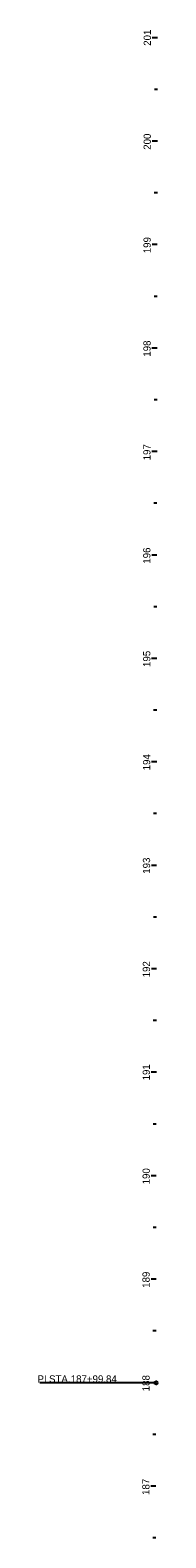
# Model space of a CAD drawing. Extents: x 1805326 to 1810276, y 297762 to 303660.
# Drawn here: x 1808551 to 1808667, y 299219 to 300677 of the extents above; entities that cross this region are included whole.
import ezdxf

# ---------------------------------------------------------------- set-up
doc = ezdxf.new("R2010")
doc.units = 0
doc.layers.add('GE_P_Alignment_100_Cardinal_Points', color=7, linetype='Continuous')
doc.layers.add('GE_P_Alignment_100_Stations', color=7, linetype='Continuous')

msp = doc.modelspace()

# ---------------------------------------------------------------- linework, layer by layer
at = {"layer": 'GE_P_Alignment_100_Cardinal_Points'}
msp.add_line((1808665.1, 299369.1), (1808552.6, 299369.2), dxfattribs=at)
msp.add_circle((1808665.1, 299369.1), 1.5, dxfattribs=at)
at = {"layer": 'GE_P_Alignment_100_Stations'}
for p, q in [((1808666.4, 300669.2), (1808661.4, 300669.2)), ((1808666.4, 300619.2), (1808663.4, 300619.2)), ((1808666.3, 300569.2), (1808661.3, 300569.2)), ((1808666.3, 300519.2), (1808663.3, 300519.2)), ((1808666.2, 300469.2), (1808661.2, 300469.2)), ((1808666.2, 300419.2), (1808663.2, 300419.2)), ((1808666.1, 300369.2), (1808661.1, 300369.2)), ((1808666.1, 300319.2), (1808663.1, 300319.2)), ((1808666, 300269.2), (1808661, 300269.2)), ((1808665.9, 300219.2), (1808662.9, 300219.2)), ((1808665.9, 300169.2), (1808660.9, 300169.2)), ((1808665.8, 300119.2), (1808662.8, 300119.2)), ((1808665.8, 300069.2), (1808660.8, 300069.2)), ((1808665.7, 300019.2), (1808662.7, 300019.2)), ((1808665.7, 299969.2), (1808660.7, 299969.2)), ((1808665.6, 299919.2), (1808662.6, 299919.2)), ((1808665.6, 299869.2), (1808660.6, 299869.2)), ((1808665.5, 299819.2), (1808662.5, 299819.2)), ((1808665.5, 299769.2), (1808660.5, 299769.2)), ((1808665.4, 299719.2), (1808662.4, 299719.2)), ((1808665.4, 299669.2), (1808660.4, 299669.2)), ((1808665.3, 299619.2), (1808662.3, 299619.2)), ((1808665.3, 299569.2), (1808660.3, 299569.2)), ((1808665.2, 299519.2), (1808662.2, 299519.2)), ((1808665.2, 299469.2), (1808660.2, 299469.2)), ((1808665.1, 299419.2), (1808662.1, 299419.2)), ((1808665.1, 299369.2), (1808660.1, 299369.2)), ((1808665, 299319.2), (1808662, 299319.2)), ((1808665, 299269.2), (1808660, 299269.2)), ((1808664.9, 299219.2), (1808661.9, 299219.2))]:
    msp.add_line(p, q, dxfattribs=at)

# ---------------------------------------------------------------- texts
at = {"layer": 'GE_P_Alignment_100_Cardinal_Points'}
for s, p in [('PI', (1808550.5, 299369.3)), (' STA. ', (1808559, 299369.3)), ('187+99.84', (1808582.6, 299369.3))]:
    msp.add_text(s, height=7, rotation=359.9418, dxfattribs=at).set_placement(p)
at = {"layer": 'GE_P_Alignment_100_Stations'}
for s, rotation, p in [('201', 89.9418, (1808660.1, 300661.4)), ('200', 89.9418, (1808660, 300560.9)), ('199', 89.9418, (1808659.9, 300460.9)), ('198', 89.9418, (1808659.8, 300360.9)), ('197', 89.9418, (1808659.7, 300260.7)), ('196', 89.9418, (1808659.6, 300160.8)), ('195', 89.9418, (1808659.5, 300061)), ('194', 89.9418, (1808659.4, 299961.1)), ('193', 89.9418, (1808659.3, 299861.1)), ('192', 89.9418, (1808659.2, 299761)), ('191', 89.9418, (1808659.1, 299661.4)), ('190', 89.9418, (1808659, 299560.9)), ('189', 89.9418, (1808658.9, 299460.9)), ('188', 89.9418, (1808658.8, 299360.9)), ('187', 89.9436, (1808658.7, 299260.7))]:
    msp.add_text(s, height=7, rotation=rotation, dxfattribs=at).set_placement(p)

doc.saveas('drawing.dxf')
